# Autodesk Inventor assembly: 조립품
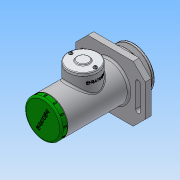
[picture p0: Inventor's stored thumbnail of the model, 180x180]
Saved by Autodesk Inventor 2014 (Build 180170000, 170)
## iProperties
Created: 2017-10
Part Number: 조립품
Document SubType Name: Assembly
Designer: net
Author: net
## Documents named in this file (19)
- C:\Users\net\Desktop\471007V1029\조립품.iam
- C:\Users\net\Desktop\471007V1029\본체.ipt
- C:\Users\net\Desktop\471007V1029\V-벨트풀리.ipt
- C:\Users\net\Desktop\471007V1029\너트 M10.ipt
- C:\Users\net\Desktop\471007V1029\멈춤링 15 x 1.ipt
- C:\Users\net\Desktop\471007V1029\멈춤링 35x1.6.ipt
- C:\Users\net\Desktop\471007V1029\베어링 15 x 35 x 11.ipt
- C:\Users\net\Desktop\471007V1029\볼트 M4 x 10.ipt
- C:\Users\net\Desktop\471007V1029\부시1.ipt
- C:\Users\net\Desktop\471007V1029\부시2.ipt
- C:\Users\net\Desktop\471007V1029\사이드 커버.ipt
- 사이드 커버.ipt
- C:\Users\net\Desktop\471007V1029\십자볼트 M3 x 10.ipt
- C:\Users\net\Desktop\471007V1029\오일 실 15 25 7.ipt
- C:\Users\net\Desktop\471007V1029\와셔 4x16.ipt
- C:\Users\net\Desktop\471007V1029\와셔 10x21.ipt
- C:\Users\net\Desktop\471007V1029\축.ipt
- C:\Users\net\Desktop\471007V1029\키 4 x 4 x 18.ipt
- C:\Users\net\Desktop\471007V1029\탑 커버.ipt
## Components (2 placed, 2 different names)
1. V-벨트풀리:1 — 각도:1
2. ISO 4017 M4 x 10:1
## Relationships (1: Angle 1)
- 각도:1 [Angle]: V-벨트풀리:1
